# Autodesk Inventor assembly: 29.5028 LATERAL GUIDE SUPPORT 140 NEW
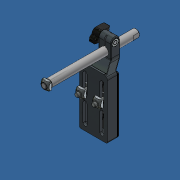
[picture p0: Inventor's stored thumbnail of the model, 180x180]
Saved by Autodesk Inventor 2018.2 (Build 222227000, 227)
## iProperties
Created: 2007-07
Part Number: 29.5028 LATERAL GUIDE SUPPORT 140 NEW
Document SubType Name: Assembly
Designer: Andy Moles
Description: LATERAL GUIDE SUPPORT 140
Author: Andy Moles
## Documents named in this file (11)
- Y:\INVENTOR LIBRARIES\PARTS LIBRARY\BELT AND ROLLER CONVEYORS\29.5028 LATERAL GUIDE SUPPORT 140 NEW.iam
- Y:\INVENTOR LIBRARIES\PARTS LIBRARY\BELT AND ROLLER CONVEYORS\SUBCOMPONENTS\29.5028 LATERAL GUIDE SUPPORT 140 WINGKNOB.ipt
- Y:\INVENTOR LIBRARIES\PARTS LIBRARY\FASTENING ELEMENTS\NUTS\21.1525 M6 HEX NUT.ipt
- Y:\INVENTOR LIBRARIES\PARTS LIBRARY\FASTENING ELEMENTS\NUTS\21.1351 M8 SQUARE NUT.ipt
- Y:\INVENTOR LIBRARIES\PARTS LIBRARY\BELT AND ROLLER CONVEYORS\SUBCOMPONENTS\29.5028 LATERAL GUIDE SUPPORT 140 ROD.ipt
- Y:\INVENTOR LIBRARIES\PARTS LIBRARY\BELT AND ROLLER CONVEYORS\SUBCOMPONENTS\29.5028 LATERAL GUIDE SUPPORT 140 BODY NEW.ipt
- Y:\INVENTOR LIBRARIES\PARTS LIBRARY\FASTENING ELEMENTS\SCREWS CAP\21.1240 M6X20.ipt
- Y:\INVENTOR LIBRARIES\PARTS LIBRARY\FASTENING ELEMENTS\WASHERS\21.1363 WASHER M6.ipt
- Y:\INVENTOR LIBRARIES\PARTS LIBRARY\FASTENING ELEMENTS\NUTS\21.1330 M6 SQUARE NUT.ipt
- Y:\INVENTOR LIBRARIES\PARTS LIBRARY\END CAPS\22.1007_1 END CAP 45x90  GRAY.iam
- 22.1007/1 END CAP 45x90  GRAY.iam
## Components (12 placed, 9 different names)
1. 29.5028 LATERAL GUIDE SUPPORT 140 BODY NEW:1 — Mate:11, Flush:1, Mate:12, Mate:13, Angle:1, Mate:14, Angle:2, Insert:5, Mate:15, Angle:3, Mate:16, Mate:17, Mate:18, Angle:4, Mate:19, Mate:20, Mate:21, Mate:22, Angle:6, Mate:25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
2. 29.5028 LATERAL GUIDE SUPPORT 140 WINGKNOB:1 — Mate:10, Mate:14, Mate:15, Angle:3
3. 21.1525 M6 HEX NUT:1 — Mate:10, Angle:2, Insert:5
4. 29.5028 LATERAL GUIDE SUPPORT 140 ROD:1 — Insert:4, Mate:13
5. 21.1351 M8 SQUARE NUT:2 — Insert:4, Angle:1
6. 21.1240  M6x20 SHCS:1 — Insert:7, Mate:18, Mate:23
7. 21.1240  M6x20 SHCS:2 — Insert:6, Mate:20, Mate:24
8. 21.1363 WASHER M6:1 — Insert:7, Mate:16, Angle:4, Flush:2
9. 21.1363 WASHER M6:2 — Insert:6, Mate:17, Mate:19, Flush:2
10. 21.1330 M6 SQUARE NUT:1 — Mate:21, Mate:23, Angle:5, Angle:6
11. 21.1330 M6 SQUARE NUT:2 — Mate:22, Mate:24, Angle:5
12. 22.1007\1 END CAP 45x90  GRAY:1 [sub-assembly] — Mate:25, Mate:26, Angle:7
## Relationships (30: Mate 17, Angle 7, Insert 4, Flush 2)
- Insert:4: 29.5028 LATERAL GUIDE SUPPORT 140 ROD:1 ↔ 21.1351 M8 SQUARE NUT:2
- Mate:10: 29.5028 LATERAL GUIDE SUPPORT 140 WINGKNOB:1 ↔ 21.1525 M6 HEX NUT:1
- Mate:11: 29.5028 LATERAL GUIDE SUPPORT 140 BODY NEW:1
- Flush:1: 29.5028 LATERAL GUIDE SUPPORT 140 BODY NEW:1
- Mate:12: 29.5028 LATERAL GUIDE SUPPORT 140 BODY NEW:1
- Mate:13: 29.5028 LATERAL GUIDE SUPPORT 140 BODY NEW:1 ↔ 29.5028 LATERAL GUIDE SUPPORT 140 ROD:1
- Angle:1: 29.5028 LATERAL GUIDE SUPPORT 140 BODY NEW:1 ↔ 21.1351 M8 SQUARE NUT:2
- Mate:14: 29.5028 LATERAL GUIDE SUPPORT 140 BODY NEW:1 ↔ 29.5028 LATERAL GUIDE SUPPORT 140 WINGKNOB:1
- Angle:2: 29.5028 LATERAL GUIDE SUPPORT 140 BODY NEW:1 ↔ 21.1525 M6 HEX NUT:1
- Insert:5: 29.5028 LATERAL GUIDE SUPPORT 140 BODY NEW:1 ↔ 21.1525 M6 HEX NUT:1
- Mate:15: 29.5028 LATERAL GUIDE SUPPORT 140 BODY NEW:1 ↔ 29.5028 LATERAL GUIDE SUPPORT 140 WINGKNOB:1
- Angle:3: 29.5028 LATERAL GUIDE SUPPORT 140 BODY NEW:1 ↔ 29.5028 LATERAL GUIDE SUPPORT 140 WINGKNOB:1
- Insert:6: 21.1240  M6x20 SHCS:2 ↔ 21.1363 WASHER M6:2
- Insert:7: 21.1240  M6x20 SHCS:1 ↔ 21.1363 WASHER M6:1
- Mate:16: 29.5028 LATERAL GUIDE SUPPORT 140 BODY NEW:1 ↔ 21.1363 WASHER M6:1
- Mate:17: 29.5028 LATERAL GUIDE SUPPORT 140 BODY NEW:1 ↔ 21.1363 WASHER M6:2
- Mate:18: 29.5028 LATERAL GUIDE SUPPORT 140 BODY NEW:1 ↔ 21.1240  M6x20 SHCS:1
- Angle:4: 29.5028 LATERAL GUIDE SUPPORT 140 BODY NEW:1 ↔ 21.1363 WASHER M6:1
- Mate:19: 29.5028 LATERAL GUIDE SUPPORT 140 BODY NEW:1 ↔ 21.1363 WASHER M6:2
- Mate:20: 29.5028 LATERAL GUIDE SUPPORT 140 BODY NEW:1 ↔ 21.1240  M6x20 SHCS:2
- Flush:2: 21.1363 WASHER M6:1 ↔ 21.1363 WASHER M6:2
- Mate:21: 29.5028 LATERAL GUIDE SUPPORT 140 BODY NEW:1 ↔ 21.1330 M6 SQUARE NUT:1
- Mate:22: 29.5028 LATERAL GUIDE SUPPORT 140 BODY NEW:1 ↔ 21.1330 M6 SQUARE NUT:2
- Mate:23: 21.1240  M6x20 SHCS:1 ↔ 21.1330 M6 SQUARE NUT:1
- Mate:24: 21.1240  M6x20 SHCS:2 ↔ 21.1330 M6 SQUARE NUT:2
- Angle:5: 21.1330 M6 SQUARE NUT:1 ↔ 21.1330 M6 SQUARE NUT:2
- Angle:6: 29.5028 LATERAL GUIDE SUPPORT 140 BODY NEW:1 ↔ 21.1330 M6 SQUARE NUT:1
- Mate:25: 29.5028 LATERAL GUIDE SUPPORT 140 BODY NEW:1 ↔ 22.1007\1 END CAP 45x90  GRAY:1
- Mate:26: 29.5028 LATERAL GUIDE SUPPORT 140 BODY NEW:1 ↔ 22.1007\1 END CAP 45x90  GRAY:1
- Angle:7: 29.5028 LATERAL GUIDE SUPPORT 140 BODY NEW:1 ↔ 22.1007\1 END CAP 45x90  GRAY:1
